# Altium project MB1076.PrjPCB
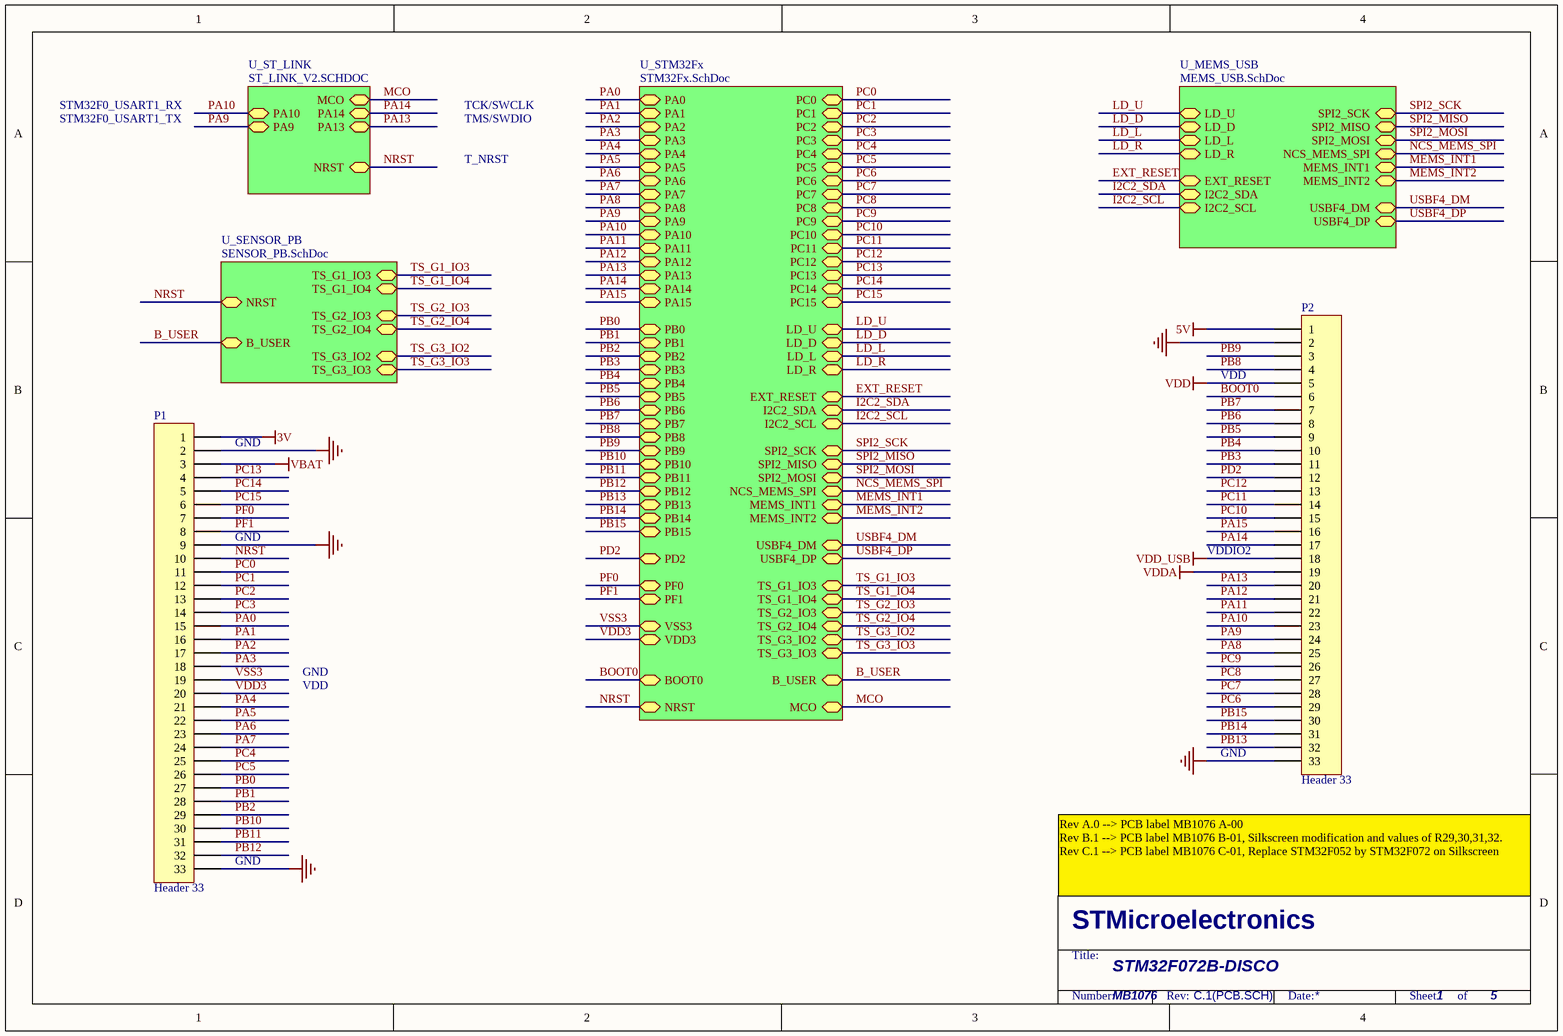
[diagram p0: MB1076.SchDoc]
5 sheets, 142 parts. Net scope: hierarchical (ports join the sheet entries above them; power ports are global).
Sheets:
  MB1076.SchDoc
    U_ST_LINK = ST_LINK_V2.SCHDOC
    U_MEMS_USB = MEMS_USB.SchDoc
    U_STM32Fx = STM32Fx.SchDoc
    U_SENSOR_PB = SENSOR_PB.SchDoc

## Sheet MB1076.SchDoc
size A4; DocumentNumber: 1; Revision: C.1(PCB.SCH); SheetNumber: 1; SheetTotal: 5; PageSetup: Record=PageOptions|CenterHorizontal=True|CenterVertical=True|PrintScale=1.00|XCorrection=1.00|YCorrection=1.00|PrintKind=1|BorderSize=5000000|LeftOffset=0|BottomOffset=0|Orientation=2|PaperLength=1000|PaperWidth=1000|Scale=100|PaperSource=15|PrintQuality=1200|MediaType=1|DitherType=10|PaperKind=A4|PrintScaleMode=1

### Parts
P1  Header 33  [HDR1X33]
P2  Header 33  [HDR1X33]

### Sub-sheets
U_MEMS_USB = MEMS_USB.SchDoc: LD_D, LD_U, LD_L, LD_R, EXT_RESET, MEMS_INT1, NCS_MEMS_SPI, MEMS_INT2, SPI2_SCK, SPI2_MISO, SPI2_MOSI, USBF4_DM, USBF4_DP, I2C2_SCL, I2C2_SDA
U_SENSOR_PB = SENSOR_PB.SchDoc: NRST, TS_G1_IO3, TS_G1_IO4, TS_G2_IO3, TS_G2_IO4, TS_G3_IO2, TS_G3_IO3, B_USER
U_ST_LINK = ST_LINK_V2.SCHDOC: PA13, PA14, NRST, MCO, PA10, PA9
U_STM32Fx = STM32Fx.SchDoc: PB8, PC5, PC4, PD2, BOOT0, NRST, PC15, PC14, PF1, PF0, MCO, VSS3, PC0, PC1, PC2, PC3, PC6, PC7, PC8, PC9, PC10, PC11, PC12, PC13, PA0, PA1, PA2, PA3, PA4, PA5, PA6, PA7, PA8, PA9, PA10, PA11, PA12, PA13, PA14, PA15, PB0, PB1, PB2, PB3, PB4, PB5, PB6, PB7, PB9, PB10, PB11, PB12, PB13, PB14, PB15, EXT_RESET, I2C2_SCL, I2C2_SDA, TS_G1_IO3, TS_G1_IO4, TS_G2_IO3, TS_G2_IO4, TS_G3_IO2, TS_G3_IO3, VDD3, B_USER, USBF4_DM, USBF4_DP, LD_D, LD_U, LD_L, LD_R, SPI2_SCK, SPI2_MISO, SPI2_MOSI, MEMS_INT1, NCS_MEMS_SPI, MEMS_INT2

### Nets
3V: P1.1
5V: P2.1
GND: P1.2 P1.9 P1.33 P2.2 P2.33
VBAT: P1.3
VDD: P2.5
VDD_USB: P2.18
VDDA: P2.19
B_USER: P1.15 ; sheet U_STM32Fx/PA0, sheet U_STM32Fx/B_USER, sheet U_SENSOR_PB/B_USER  [also labelled PA0]
BOOT0: P2.6 ; sheet U_STM32Fx/BOOT0
EXT_RESET: P1.26 ; sheet U_MEMS_USB/EXT_RESET, sheet U_STM32Fx/PC5, sheet U_STM32Fx/EXT_RESET  [also labelled PC5]
I2C2_SCL: P1.30 ; sheet U_MEMS_USB/I2C2_SCL, sheet U_STM32Fx/PB10, sheet U_STM32Fx/I2C2_SCL  [also labelled PB10]
I2C2_SDA: P1.31 ; sheet U_MEMS_USB/I2C2_SDA, sheet U_STM32Fx/PB11, sheet U_STM32Fx/I2C2_SDA  [also labelled PB11]
LD_D: P2.28 ; sheet U_MEMS_USB/LD_D, sheet U_STM32Fx/PC7, sheet U_STM32Fx/LD_D  [also labelled PC7]
LD_L: P2.27 ; sheet U_MEMS_USB/LD_L, sheet U_STM32Fx/PC8, sheet U_STM32Fx/LD_L  [also labelled PC8]
LD_R: P2.26 ; sheet U_MEMS_USB/LD_R, sheet U_STM32Fx/PC9, sheet U_STM32Fx/LD_R  [also labelled PC9]
LD_U: P2.29 ; sheet U_MEMS_USB/LD_U, sheet U_STM32Fx/PC6, sheet U_STM32Fx/LD_U  [also labelled PC6]
MCO: sheet U_ST_LINK/MCO, sheet U_STM32Fx/MCO
MEMS_INT1: P1.12 ; sheet U_MEMS_USB/MEMS_INT1, sheet U_STM32Fx/PC1, sheet U_STM32Fx/MEMS_INT1  [also labelled PC1]
MEMS_INT2: P1.13 ; sheet U_MEMS_USB/MEMS_INT2, sheet U_STM32Fx/PC2, sheet U_STM32Fx/MEMS_INT2  [also labelled PC2]
NCS_MEMS_SPI: P1.11 ; sheet U_MEMS_USB/NCS_MEMS_SPI, sheet U_STM32Fx/PC0, sheet U_STM32Fx/NCS_MEMS_SPI  [also labelled PC0]
NRST: P1.10 ; sheet U_ST_LINK/NRST, sheet U_STM32Fx/NRST, sheet U_SENSOR_PB/NRST
PA1: P1.16 ; sheet U_STM32Fx/PA1
PA2: P1.17 ; sheet U_STM32Fx/PA2
PA3: P1.18 ; sheet U_STM32Fx/PA3
PA4: P1.21 ; sheet U_STM32Fx/PA4
PA5: P1.22 ; sheet U_STM32Fx/PA5
PA6: P1.23 ; sheet U_STM32Fx/PA6
PA7: P1.24 ; sheet U_STM32Fx/PA7
PA8: P2.25 ; sheet U_STM32Fx/PA8
PA9: P2.24 ; sheet U_ST_LINK/PA9, sheet U_STM32Fx/PA9
PA10: P2.23 ; sheet U_ST_LINK/PA10, sheet U_STM32Fx/PA10
PA11: P2.22 ; sheet U_STM32Fx/PA11
PA12: P2.21 ; sheet U_STM32Fx/PA12
PA13: P2.20 ; sheet U_ST_LINK/PA13, sheet U_STM32Fx/PA13
PA14: P2.17 ; sheet U_ST_LINK/PA14, sheet U_STM32Fx/PA14
PA15: P2.16 ; sheet U_STM32Fx/PA15
PB0: P1.27 ; sheet U_STM32Fx/PB0
PB1: P1.28 ; sheet U_STM32Fx/PB1
PB2: P1.29 ; sheet U_STM32Fx/PB2
PB3: P2.11 ; sheet U_STM32Fx/PB3
PB4: P2.10 ; sheet U_STM32Fx/PB4
PB5: P2.9 ; sheet U_STM32Fx/PB5
PB6: P2.8 ; sheet U_STM32Fx/PB6
PB7: P2.7 ; sheet U_STM32Fx/PB7
PB8: P2.4 ; sheet U_STM32Fx/PB8
PB9: P2.3 ; sheet U_STM32Fx/PB9
PB12: P1.32 ; sheet U_STM32Fx/PB12
PB13: P2.32 ; sheet U_MEMS_USB/SPI2_SCK, sheet U_STM32Fx/PB13, sheet U_STM32Fx/SPI2_SCK  [also labelled SPI2_SCK]
PB14: P2.31 ; sheet U_MEMS_USB/SPI2_MISO, sheet U_STM32Fx/PB14, sheet U_STM32Fx/SPI2_MISO  [also labelled SPI2_MISO]
PB15: P2.30 ; sheet U_MEMS_USB/SPI2_MOSI, sheet U_STM32Fx/PB15, sheet U_STM32Fx/SPI2_MOSI  [also labelled SPI2_MOSI]
PC3: P1.14 ; sheet U_STM32Fx/PC3
PC4: P1.25 ; sheet U_STM32Fx/PC4
PC10: P2.15 ; sheet U_STM32Fx/PC10
PC11: P2.14 ; sheet U_STM32Fx/PC11
PC12: P2.13 ; sheet U_STM32Fx/PC12
PC13: P1.4 ; sheet U_STM32Fx/PC13
PC14: P1.5 ; sheet U_STM32Fx/PC14
PC15: P1.6 ; sheet U_STM32Fx/PC15
PD2: P2.12 ; sheet U_STM32Fx/PD2
PF0: P1.7 ; sheet U_STM32Fx/PF0
PF1: P1.8 ; sheet U_STM32Fx/PF1
TS_G1_IO3: sheet U_STM32Fx/TS_G1_IO3, sheet U_SENSOR_PB/TS_G1_IO3
TS_G1_IO4: sheet U_STM32Fx/TS_G1_IO4, sheet U_SENSOR_PB/TS_G1_IO4
TS_G2_IO3: sheet U_STM32Fx/TS_G2_IO3, sheet U_SENSOR_PB/TS_G2_IO3
TS_G2_IO4: sheet U_STM32Fx/TS_G2_IO4, sheet U_SENSOR_PB/TS_G2_IO4
TS_G3_IO2: sheet U_STM32Fx/TS_G3_IO2, sheet U_SENSOR_PB/TS_G3_IO2
TS_G3_IO3: sheet U_STM32Fx/TS_G3_IO3, sheet U_SENSOR_PB/TS_G3_IO3
USBF4_DM: sheet U_MEMS_USB/USBF4_DM, sheet U_STM32Fx/USBF4_DM
USBF4_DP: sheet U_MEMS_USB/USBF4_DP, sheet U_STM32Fx/USBF4_DP
VDD3: P1.20 ; sheet U_STM32Fx/VDD3
VSS3: P1.19 ; sheet U_STM32Fx/VSS3

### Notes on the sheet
- STM32F0_USART1_RX
- TCK/SWCLK
- STM32F0_USART1_TX
- TMS/SWDIO
- T_NRST
- VDD
- (near P1) GND
- VDDIO2
- GND
- Rev A.0 --> PCB label MB1076 A-00
  Rev B.1 --> PCB label MB1076 B-01, Silkscreen modification and values of R29,30,31,32.
  Rev C.1 --> PCB label MB1076 C-01, Replace STM32F052 by STM32F072 on Silkscreen
- STM32F072B-DISCO
- MB1076
- 1

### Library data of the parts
P1 P2 = Header 33: Header, 33-Pin

## Sheet ST_LINK_V2.SCHDOC
size A4; DocumentNumber: 2; Revision: C.1(PCB.SCH); SheetNumber: 2; SheetTotal: 5
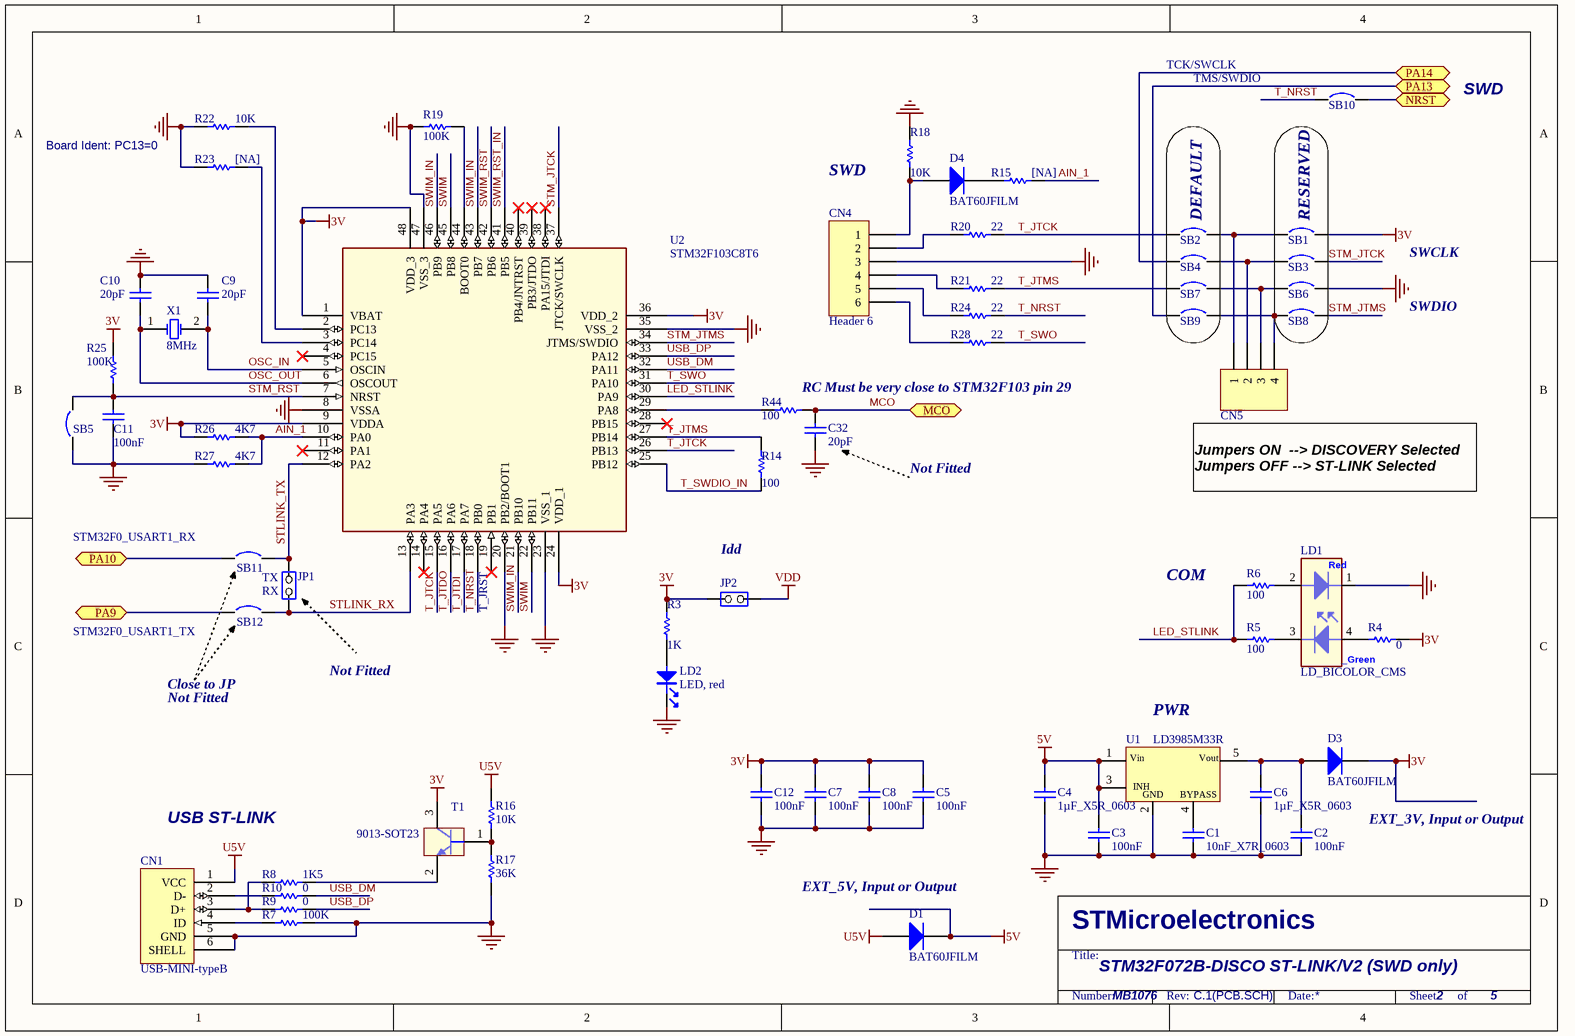
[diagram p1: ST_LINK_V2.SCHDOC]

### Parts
C1  10nF_X7R_0603  [0603C]
C2  100nF  [0402C]
C3  100nF  [0402C]
C4  1µF_X5R_0603  [0603C]
C5  100nF  [0402C]
C6  1µF_X5R_0603  [0603C]
C7  100nF  [0402C]
C8  100nF  [0402C]
C9  20pF  [0402C]
C10  20pF  [0402C]
C11  100nF  [0402C]
C12  100nF  [0402C]
C32  20pF  [0402C]
CN1  USB-MINI-typeB  [USB-MINI-B-SMD]
CN4  Header 6  [HDR1X6]
CN5  Header 4  [Header 4]  (value not drawn)
D1  BAT60JFILM  [SOD323/A]
D3  BAT60JFILM  [SOD323/A]
D4  BAT60JFILM  [SOD323/A]
JP1  JP2  [SIP2/2.54]  (value not drawn)
JP2  (no value)  [SIP2/2.54]
LD1  LD_BICOLOR_CMS  [HSMF-A201]
LD2  LED, red  [0603D]
R3  1K  [0402R]
R4  0  [0402R]
R5  100  [0402R]
R6  100  [0402R]
R7  100K  [0402R]
R8  1K5  [0402R]
R9  0  [0402R]
R10  0  [0402R]
R14  100  [0402R]
R15  [NA]  [0402R]
R16  10K  [0402R]
R17  36K  [0402R]
R18  10K  [0402R]
R19  100K  [0402R]
R20  22  [0402R]
R21  22  [0402R]
R22  10K  [0402R]
R23  [NA]  [0402R]
R24  22  [0402R]
R25  100K  [0402R]
R26  4K7  [0402R]
R27  4K7  [0402R]
R28  22  [0402R]
R44  100  [0402R]
SB1  Circuit Breaker  [JP2_SMD]  (value not drawn)
SB2  Circuit Breaker  [JP2_SMD]  (value not drawn)
SB3  Circuit Breaker  [JP2_SMD]  (value not drawn)
SB4  Circuit Breaker  [JP2_SMD]  (value not drawn)
SB5  Circuit Breaker  [JP2_SMD]  (value not drawn)
SB6  Circuit Breaker  [JP2_SMD]  (value not drawn)
SB7  Circuit Breaker  [JP2_SMD]  (value not drawn)
SB8  Circuit Breaker  [JP2_SMD]  (value not drawn)
SB9  Circuit Breaker  [JP2_SMD]  (value not drawn)
SB10  Circuit Breaker  [JP2_SMD]  (value not drawn)
SB11  Circuit Breaker  [JP2_SMD]  (value not drawn)
SB12  Circuit Breaker  [JP2_SMD]  (value not drawn)
T1  9013-SOT23  [SOT-23]
U1  LD3985M33R  [SOT-23-5L]
U2  STM32F103C8T6  [QFP48 7X7]
X1  8MHz  [XTAL1]

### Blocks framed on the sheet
DEFAULT: SB2 SB4 SB7 SB9
RESERVED: SB1 SB3 SB6 SB8

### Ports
MCO, NRST, PA9, PA10, PA13, PA14

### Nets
3V: C5.2 C7.2 C8.2 C12.2 D3.2(K) JP2.1(COMMON) R3.2 R4.2 R25.2 R26.1 SB1.2 T1.3(C) U2.1(VBAT) U2.9(VDDA) U2.24(VDD_1) U2.36(VDD_2) U2.48(VDD_3)
5V: C3.2 C4.2 D1.2(K) U1.1(Vin) U1.3(CE)
GND: C1.1 C2.1 C3.1 C4.1 C5.1 C6.2 C7.1 C8.1 C9.2 C10.2 C11.1 C12.1 C32.1 CN1.5(GND) CN1.6(SHELL) CN4.3 LD1.1 LD2.2 R7.2 R17.1 R18.2 R19.1 R22.1 R23.1 R27.1 SB5.1 SB6.2 U1.2(GND) U2.8(VSSA) U2.20(PB2/BOOT1) U2.23(VSS_1) U2.35(VSS_2) U2.47(VSS_3)
U5V: CN1.1(VCC) D1.1(A) R16.2
VDD: JP2.2(NO)
AIN_1: R15.2 R26.2 R27.2 U2.10(PA0)
LED_STLINK: R5.1 R6.1 U2.30(PA9)
MCO: C32.2 R44.2 ; port MCO
NRST: SB10.2 ; port NRST
OSC_IN: C9.1 U2.5(OSCIN) X1.2(OSC2)
OSC_OUT: C10.1 U2.6(OSCOUT) X1.1(OSC1)
PA9: SB12.1 ; port PA9
PA10: SB11.1 ; port PA10
PA13: SB9.1 ; port PA13
PA14: SB4.1 ; port PA14
STLINK_RX: JP1.1(COMMON) SB12.2 U2.13(PA3)
STLINK_TX: JP1.2(NO) SB11.2 U2.12(PA2)
STM_JTCK: SB3.2 U2.37(JTCK/SWCLK)
STM_JTMS: SB8.2 U2.34(JTMS/SWDIO)
STM_RST: C11.2 R25.1 SB5.2 U2.7(NRST)
SWIM: U2.22(PB11) U2.45(PB8)
SWIM_IN: U2.21(PB10) U2.43(PB7) U2.46(PB9)
SWIM_RST: U2.42(PB6)
SWIM_RST_IN: U2.41(PB5)
T_JTCK: R20.2 SB2.1 U2.15(PA5) U2.26(PB13)
T_JTDI: U2.17(PA7)
T_JTDO: U2.16(PA6)
T_JTMS: R14.2 R21.2 SB7.1 U2.27(PB14)
T_NRST: R24.2 SB10.1 U2.18(PB0)
T_SWDIO_IN: R14.1 U2.25(PB12)
T_SWO: R28.2 U2.31(PA10)
USB_DM: R10.2 U2.32(PA11)
USB_DP: R9.2 U2.33(PA12)
NetC1_2: C1.2 U1.4(BYPASS)
NetC2_2: C2.2 C6.1 D3.1(A) U1.5(Vout)
NetCN1_2: CN1.2(D-) R10.1
NetCN1_3: CN1.3(D+) R8.1 R9.1
NetCN1_4: CN1.4(ID) R7.1
NetCN4_1: CN4.1 D4.1(A) R18.1
NetCN4_2: CN4.2 R20.1
NetCN4_4: CN4.4 R21.1
NetCN4_5: CN4.5 R24.1
NetCN4_6: CN4.6 R28.1
NetCN5_1: CN5.1 SB1.1 SB2.2
NetCN5_2: CN5.2 SB3.1 SB4.2
NetCN5_3: CN5.3 SB6.1 SB7.2
NetCN5_4: CN5.4 SB8.1 SB9.2
NetD4_2: D4.2(K) R15.1
NetLD1_2: LD1.2 R6.2
NetLD1_3: LD1.3 R5.2
NetLD1_4: LD1.4 R4.1
NetLD2_1: LD2.1 R3.1
NetR8_2: R8.2 T1.2(E)
NetR16_1: R16.1 R17.2 T1.1(B)
NetR19_2: R19.2 U2.44(BOOT0)
NetR22_2: R22.2 U2.2(PC13)
NetR23_2: R23.2 U2.3(PC14)
NetR44_1: R44.1 U2.29(PA8)

Not connected (* = marked no-connect by the designer): U2 4(PC15)* 11(PA1)* 14(PA4)* 19(PB1)* 28(PB15)* 38(PA15/JTDI)* 39(PB3/JTDO)* 40(PB4/JNTRST)*

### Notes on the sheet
- TCK/SWCLK
- TMS/SWDIO
- SWD
- Board Ident: PC13=0
- SWCLK
- SWDIO
- (near R44) RC Must be very close to STM32F103 pin 29
- Not Fitted
- Jumpers ON  --> DISCOVERY Selected
  Jumpers OFF --> ST-LINK Selected
- STM32F0_USART1_RX
- TX
- (near JP2) Idd
- COM
- STM32F0_USART1_TX
- RX
- (near U2) T_JRST
- Close to JP
- (near U1) PWR
- USB ST-LINK
- EXT_3V, Input or Output
- (near D1) EXT_5V, Input or Output
- STM32F072B-DISCO ST-LINK/V2 (SWD only)
- MB1076

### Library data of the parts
C1 = CAP SMD 0603  X7R 10000PF 50V 10%: 0603  X7R 10NF; Order code RS: 2040779; Rated voltage: 50V; Tolerance: 10%
C2 C3 C5 C7 C8 C11 C12 = Capacitor_ST: Capacitor 0402 / 0603 / 0805
C4 C6 = CAP SMD 0603  X5R 1µF 25V 10%: 0603  X5R 1µF; Rated voltage: 25V; Tolerance: 10%
C9 C10 C32 = Capacitor_ST: Capacitor 0402 / 0603 / 0805; Value: 100nF
CN1 = USB-MINI-typeB connector: Manuf_Part_1: 5075BMR-05-SM; Manuf_Part_2: 218205M1110T; Manuf_2: lyconn; Description: USB,MINI-USB-5P/F, 5075BMR-05-M
CN4 = Header 6: Header, 6-Pin
CN5 = Header 4: Header, 4-Pin
D1 D3 D4 = BAT60JFILM: Manuf_1: STM; Provided: ST; ECCN_US/EU: EAR99/NEC
JP1 = JP2: Fitted: NO
JP2 = JP2
LD1 = LD_BICOLOR_CMS: Bicolor Led; Manuf_Part_1: HSMF-A201-A00J1; Manuf_1: Avago Technologies; Manuf_2: everluck; Manuf_Part_2: LE-RGW35280; Ref St: xxxxxx
LD2 = LED_red: LED, red, 0603; Manuf_1: everlight; Manuf_Part_1: 19-213-R6C-AP1Q2B/3T; Description: LED,red,0603,19-213-R6C-AP1Q2B/3T,everlight
R3-R10 R14 R17 R19-R21 R24-R28 R44 = Resistor_ST: Resistor 0402 / 0603 / 0805; Description: Resistor 0402 or 0603 or 0805; Value: 10K
R15 R23 = Resistor_ST: Resistor 0402 / 0603 / 0805; Description: Resistor 0402 or 0603 or 0805; Value: 10K; Fitted: NO
R16 R18 R22 = Resistor_ST: Resistor 0402 / 0603 / 0805; Description: Resistor 0402 or 0603 or 0805
SB1 SB3 SB6 SB8 SB10 = Circuit Breaker: Solder: YES
SB2 SB4 SB5 SB7 SB9 SB11 SB12 = Circuit Breaker: Solder: NO
T1 = 9013-SOT23: NPN Bipolar Transistor; Description: NPN Bipolar Transistor, SOT-23 Footprint
U1 = LD3985M33R: Ultra low drop-low noise BiCMOS voltage, regulators low ESR capacitors compatible; Manuf_1: STM; Provided: ST; Ref St: 9176161; ECCN_US/EU: EAR99/NEC
U2 = STM32F103C8T6: Medium-density performance line ARM-based 32-bit MCU with 64KB Flash; Manuf_1: STM; Ref St: 9175981; Provided: ST; ECCN_US/EU: 3A991A2/NEC
X1 = XTAL: Crystal Oscillator,8Mhz,20PF,20PPM,-10-70 degree,DIP,HC-49S; Manuf_Part_1: 9SL8000020AFXHF0

## Sheet MEMS_USB.SchDoc
size A4; DocumentNumber: 6; Revision: C.1(PCB.SCH); SheetNumber: 4; SheetTotal: 5
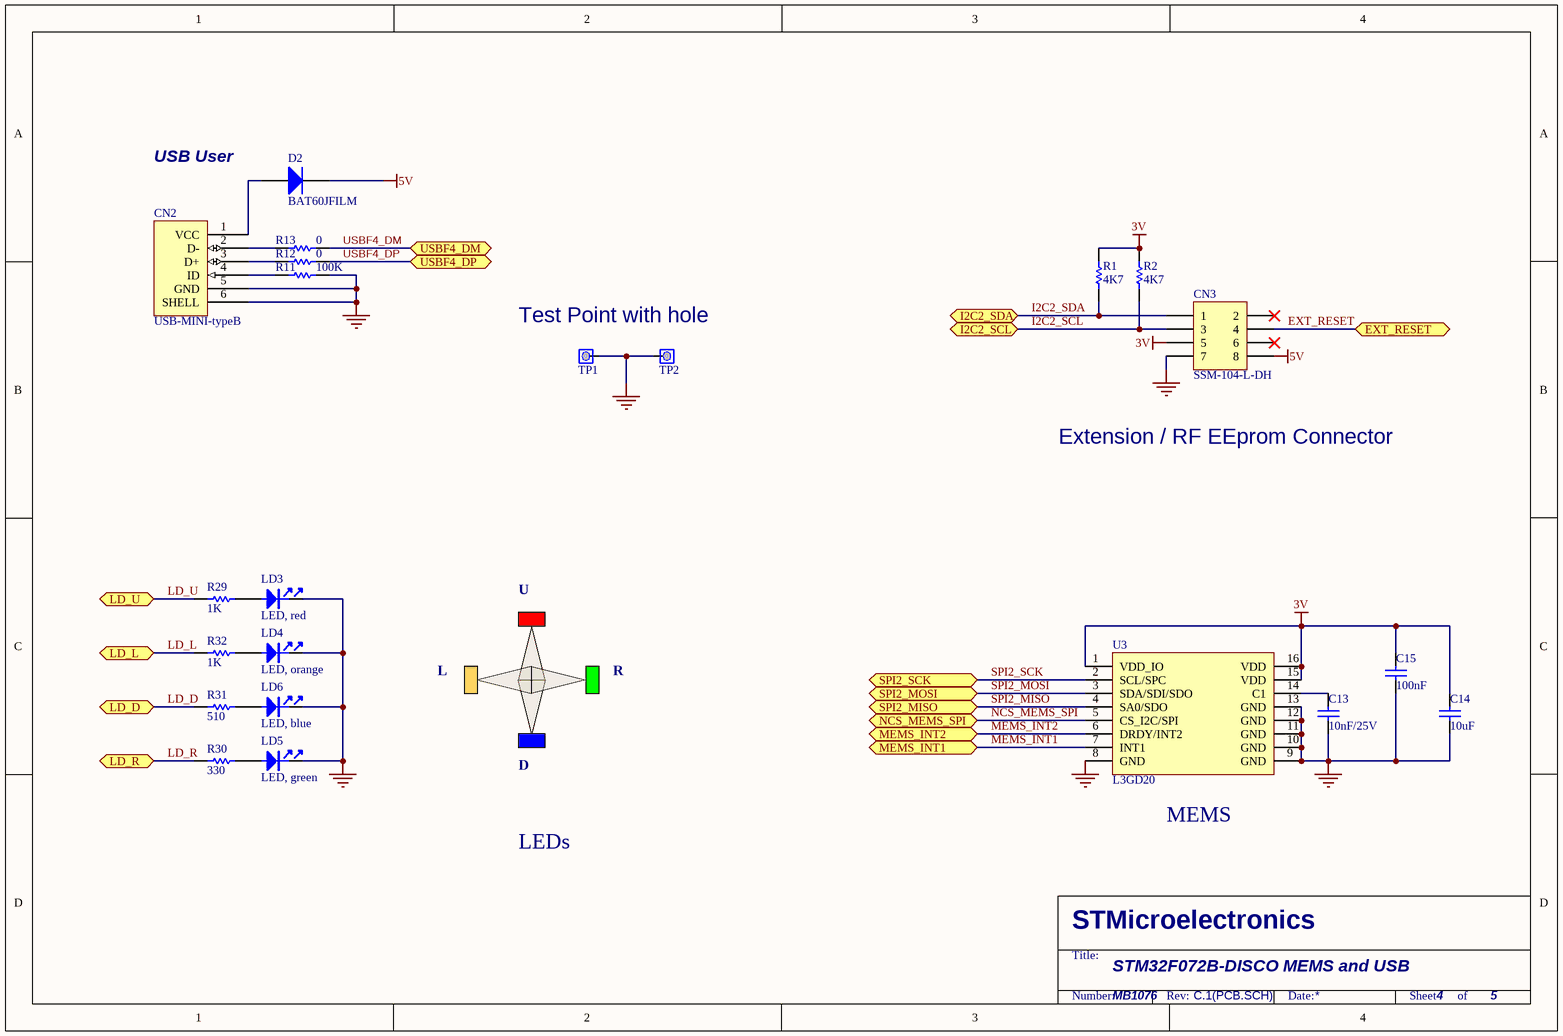
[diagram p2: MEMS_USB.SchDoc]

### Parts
C13  10nF/25V  [0603C]
C14  10uF  [0603C]
C15  100nF  [0402C]
CN2  USB-MINI-typeB  [USB-MINI-B-SMD]
CN3  SSM-104-L-DH  [SSM-104-L-DH]
D2  BAT60JFILM  [SOD323/A]
LD3  LED, red  [0603D]
LD4  LED, orange  [0603D]
LD5  LED, green  [0603D]
LD6  LED, blue  [0603D]
R1  4K7  [0402R]
R2  4K7  [0402R]
R11  100K  [0402R]
R12  0  [0402R]
R13  0  [0402R]
R29  1K  [0603R]
R30  330  [0603R]
R31  510  [0603R]
R32  1K  [0603R]
TP1  Test point 1 pin with hole  [SIP1/2.54]  (value not drawn)
TP2  Test point 1 pin with hole  [SIP1/2.54]  (value not drawn)
U3  L3GD20  [LGA16-4x4]

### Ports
EXT_RESET, I2C2_SCL, I2C2_SDA, LD_D, LD_L, LD_R, LD_U, MEMS_INT1, MEMS_INT2, NCS_MEMS_SPI, SPI2_MISO, SPI2_MOSI, SPI2_SCK, USBF4_DM, USBF4_DP

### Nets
3V: C14.2 C15.2 CN3.5 R1.2 R2.2 U3.1(VDD_IO) U3.15(VDD) U3.16(VDD)
5V: CN3.8 D2.2(K)
GND: C13.1 C14.1 C15.1 CN2.5(GND) CN2.6(SHELL) CN3.7 LD3.2 LD4.2 LD5.2 LD6.2 R11.2 TP1.1(COMMON) TP2.1(COMMON) U3.8(GND) U3.9(GND) U3.10(GND) U3.11(GND) U3.12(GND) U3.13(GND)
EXT_RESET: CN3.4 ; port EXT_RESET
I2C2_SCL: CN3.3 R2.1 ; port I2C2_SCL
I2C2_SDA: CN3.1 R1.1 ; port I2C2_SDA
LD_D: R31.1 ; port LD_D
LD_L: R32.1 ; port LD_L
LD_R: R30.1 ; port LD_R
LD_U: R29.1 ; port LD_U
MEMS_INT1: U3.7(INT1) ; port MEMS_INT1
MEMS_INT2: U3.6(DRDY/INT2) ; port MEMS_INT2
NCS_MEMS_SPI: U3.5(CS_I2C/SPI) ; port NCS_MEMS_SPI
SPI2_MISO: U3.4(SA0/SDO) ; port SPI2_MISO  [project net PB14]
SPI2_MOSI: U3.3(SDA/SDI/SDO) ; port SPI2_MOSI  [project net PB15]
SPI2_SCK: U3.2(SCL/SPC) ; port SPI2_SCK  [project net PB13]
USBF4_DM: R13.2 ; port USBF4_DM
USBF4_DP: R12.2 ; port USBF4_DP
NetC13_2: C13.2 U3.14(C1)
NetCN2_1: CN2.1(VCC) D2.1(A)
NetCN2_2: CN2.2(D-) R13.1
NetCN2_3: CN2.3(D+) R12.1
NetCN2_4: CN2.4(ID) R11.1
NetLD3_1: LD3.1 R29.2
NetLD4_1: LD4.1 R32.2
NetLD5_1: LD5.1 R30.2
NetLD6_1: LD6.1 R31.2

Not connected (* = marked no-connect by the designer): CN3 2* 6*

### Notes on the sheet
- USB User
- Test Point with hole
- Extension / RF EEprom Connector
- U
- L
- R
- D
- LEDs
- (near U3) MEMS
- STM32F072B-DISCO MEMS and USB
- MB1076

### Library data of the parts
C13 C14 = CAP: Capacitor; Value: 100nF
C15 = Capacitor_ST: Capacitor 0402 / 0603 / 0805
CN2 = USB-MINI-typeB connector: Manuf_Part_1: 5075BMR-05-SM
CN3 = SSM-104-L-DH: Header, 5-Pin, Dual row
D2 = BAT60JFILM: as D1 on sheet ST_LINK_V2
LD3 = LED_red: as LD2 on sheet ST_LINK_V2
LD4 = LED_orange: LED, orange, 0603; Manuf_1: everlight; Manuf_Part_1: 19-217/S2C-AM2N2VY/3T; Description: LED,orange,0603,19-217/S2C-AM2N2VY/3T,everlight
LD5 = LED_green: LED, green, 0603; Manuf_1: everlight; Manuf_Part_1: 19-213SYGC/S530-E2/TR8; Description: LED,green,0603,19-213SYGC/S530-E2/TR8,everlight
LD6 = LED_blue: LED, blue, 0603; Manuf_1: everlight; Manuf_Part_1: 19-217/BHC-ZL1M2RY/3T; Description: LED,Blue,0603,19-217/BHC-ZL1M2RY/3T,everlight
R1 R2 R11-R13 R29-R32 = Resistor_ST: as R3 on sheet ST_LINK_V2
TP1 TP2 = TP1: Test Point; Fitted: NO
U3 = L3GD20: MEMS motion sensor three-axis digital output gyroscopeelerometer; Manuf_1: STM; Manuf_Part_1: L3GD20TR; Provided: ST; Ref St: 9177042; ECCN_US/EU: EAR99/NEC

## Sheet STM32Fx.SchDoc
size A4; DocumentNumber: 3; Revision: C.1(PCB.SCH); SheetNumber: 3; SheetTotal: 5
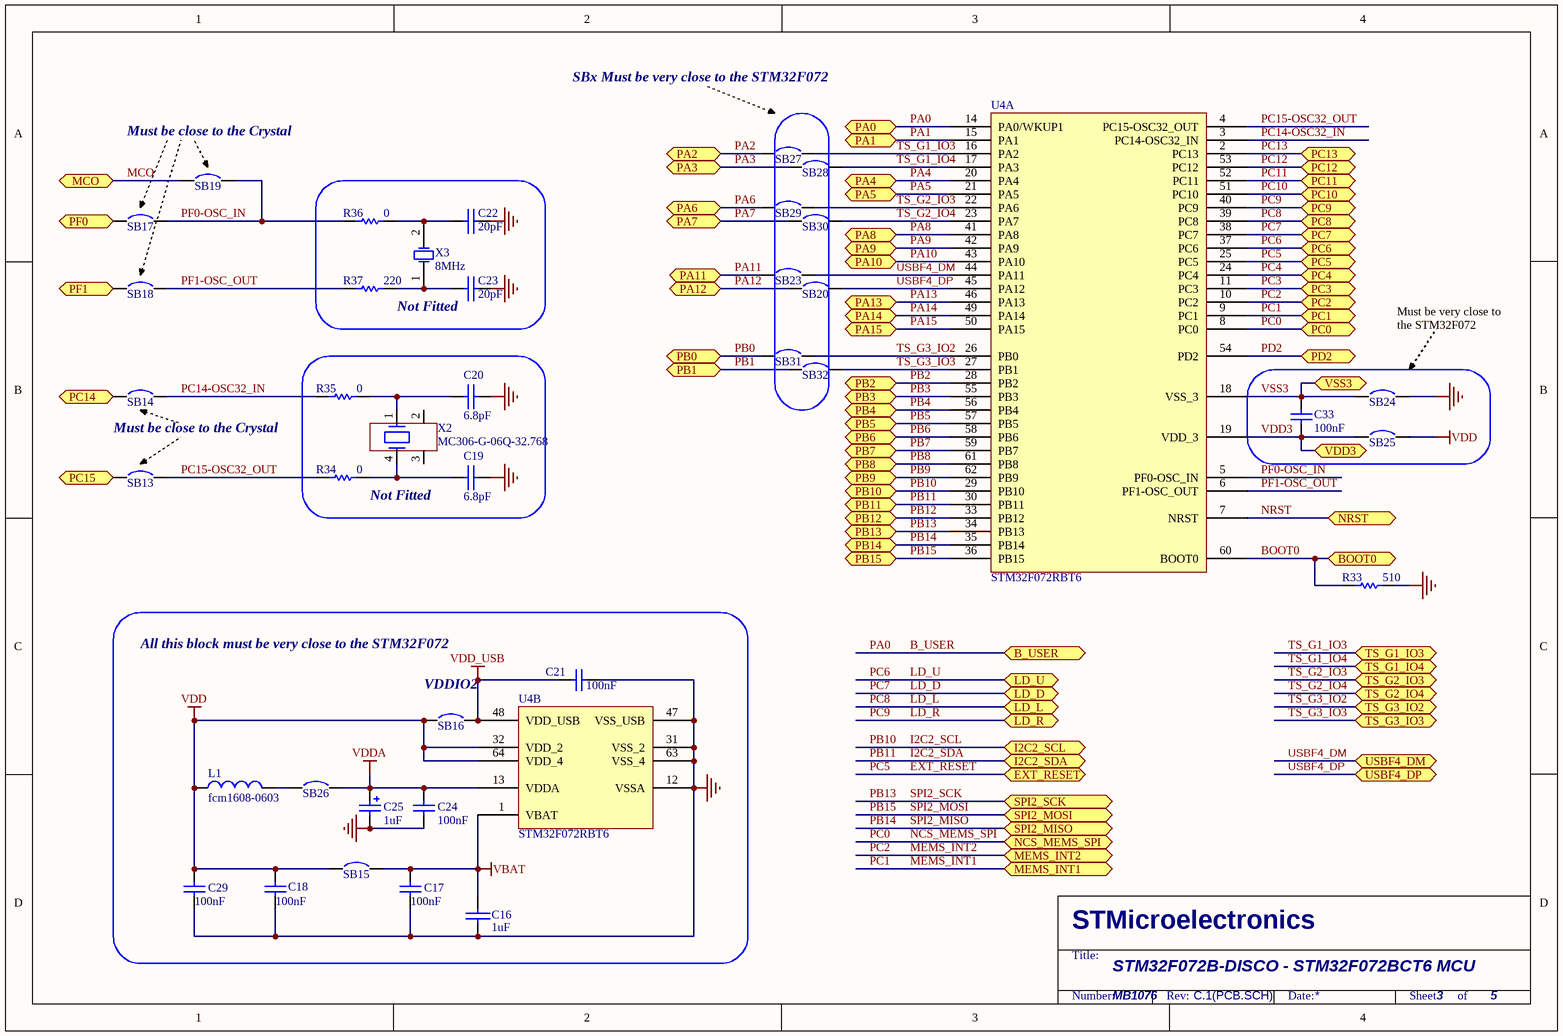
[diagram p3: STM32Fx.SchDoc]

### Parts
C16  1uF  [0603C]
C17  100nF  [0603C]
C18  100nF  [0603C]
C19  6.8pF  [0603C]
C20  6.8pF  [0603C]
C21  100nF  [0603C]
C22  20pF  [0603C]
C23  20pF  [0603C]
C24  100nF  [0603C]
C25  1uF  [CASE-AA]
C29  100nF  [0603C]
C33  100nF  [0402C]
L1  fcm1608-0603  [0603L]
R33  510  [0402R]
R34  0  [0402R]
R35  0  [0402R]
R36  0  [0402R]
R37  220  [0402R]
SB13  Circuit Breaker  [JP2_SMD]  (value not drawn)
SB14  Circuit Breaker  [JP2_SMD]  (value not drawn)
SB15  Circuit Breaker  [JP2_SMD]  (value not drawn)
SB16  Circuit Breaker  [JP2_SMD]  (value not drawn)
SB17  Circuit Breaker  [JP2_SMD]  (value not drawn)
SB18  Circuit Breaker  [JP2_SMD]  (value not drawn)
SB19  Circuit Breaker  [JP2_SMD]  (value not drawn)
SB20  Circuit Breaker  [JP2_SMD]  (value not drawn)
SB23  Circuit Breaker  [JP2_SMD]  (value not drawn)
SB24  Circuit Breaker  [JP2_SMD]  (value not drawn)
SB25  Circuit Breaker  [JP2_SMD]  (value not drawn)
SB26  Circuit Breaker  [JP2_SMD]  (value not drawn)
SB27  Circuit Breaker  [JP2_SMD]  (value not drawn)
SB28  Circuit Breaker  [JP2_SMD]  (value not drawn)
SB29  Circuit Breaker  [JP2_SMD]  (value not drawn)
SB30  Circuit Breaker  [JP2_SMD]  (value not drawn)
SB31  Circuit Breaker  [JP2_SMD]  (value not drawn)
SB32  Circuit Breaker  [JP2_SMD]  (value not drawn)
U4  STM32F072RBT6  [QFP64]  (parts A,B of 2)
X2  MC306-G-06Q-32.768  [MC306-CRYSTAL]
X3  8MHz  [XTAL1]

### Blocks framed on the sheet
Not Fitted: C22 C23 R36 R37 X3
Not Fitted: C19 C20 R34 R35 X2

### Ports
B_USER, BOOT0, EXT_RESET, I2C2_SCL, I2C2_SDA, LD_D, LD_L, LD_R, LD_U, MCO, MEMS_INT1, MEMS_INT2, NCS_MEMS_SPI, NRST, PA0, PA1, PA2, PA3, PA4, PA5, PA6, PA7, PA8, PA9, PA10, PA11, PA12, PA13, PA14, PA15, PB0, PB1, PB2, PB3, PB4, PB5, PB6, PB7, PB8, PB9, PB10, PB11, PB12, PB13, PB14, PB15, PC0, PC1, PC2, PC3, PC4, PC5, PC6, PC7, PC8, PC9, PC10, PC11, PC12, PC13, PC14, PC15, PD2, PF0, PF1, SPI2_MISO, SPI2_MOSI, SPI2_SCK, TS_G1_IO3, TS_G1_IO4, TS_G2_IO3, TS_G2_IO4, TS_G3_IO2, TS_G3_IO3, USBF4_DM, USBF4_DP, VDD3, VSS3

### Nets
GND: C16.2 C17.1 C18.2 C19.2 C20.2 C21.1 C22.1 C23.1 C24.1 C25.2 C29.1 R33.2 SB24.2 U4.12(VSSA) U4.31(VSS_2) U4.47(VSS_USB) U4.63(VSS_4)
VBAT: C16.1 C17.2 SB15.2 U4.1(VBAT)
VDD: C18.1 C29.2 L1.1 SB15.1 SB16.1 SB25.2 U4.32(VDD_2) U4.64(VDD_4)
VDD_USB: C21.2 SB16.2 U4.48(VDD_USB)
VDDA: C24.2 C25.1 SB26.2 U4.13(VDDA)
B_USER: U4.14(PA0/WKUP1) ; port PA0, port B_USER  [also labelled PA0]
BOOT0: R33.1 U4.60(BOOT0) ; port BOOT0
EXT_RESET: U4.25(PC5) ; port PC5, port EXT_RESET  [also labelled PC5]
I2C2_SCL: U4.29(PB10) ; port PB10, port I2C2_SCL  [also labelled PB10]
I2C2_SDA: U4.30(PB11) ; port PB11, port I2C2_SDA  [also labelled PB11]
LD_D: U4.38(PC7) ; port PC7, port LD_D  [also labelled PC7]
LD_L: U4.39(PC8) ; port PC8, port LD_L  [also labelled PC8]
LD_R: U4.40(PC9) ; port PC9, port LD_R  [also labelled PC9]
LD_U: U4.37(PC6) ; port PC6, port LD_U  [also labelled PC6]
MCO: SB19.1 ; port MCO
MEMS_INT1: U4.9(PC1) ; port PC1, port MEMS_INT1  [also labelled PC1]
MEMS_INT2: U4.10(PC2) ; port PC2, port MEMS_INT2  [also labelled PC2]
NCS_MEMS_SPI: U4.8(PC0) ; port PC0, port NCS_MEMS_SPI  [also labelled PC0]
NRST: U4.7(NRST) ; port NRST
PA1: U4.15(PA1) ; port PA1
PA2: SB27.1 ; port PA2
PA3: SB28.1 ; port PA3
PA4: U4.20(PA4) ; port PA4
PA5: U4.21(PA5) ; port PA5
PA6: SB29.1 ; port PA6
PA7: SB30.1 ; port PA7
PA8: U4.41(PA8) ; port PA8
PA9: U4.42(PA9) ; port PA9
PA10: U4.43(PA10) ; port PA10
PA11: SB23.1 ; port PA11
PA12: SB20.1 ; port PA12
PA13: U4.46(PA13) ; port PA13
PA14: U4.49(PA14) ; port PA14
PA15: U4.50(PA15) ; port PA15
PB0: SB31.1 ; port PB0
PB1: SB32.1 ; port PB1
PB2: U4.28(PB2) ; port PB2
PB3: U4.55(PB3) ; port PB3
PB4: U4.56(PB4) ; port PB4
PB5: U4.57(PB5) ; port PB5
PB6: U4.58(PB6) ; port PB6
PB7: U4.59(PB7) ; port PB7
PB8: U4.61(PB8) ; port PB8
PB9: U4.62(PB9) ; port PB9
PB12: U4.33(PB12) ; port PB12
PB13: U4.34(PB13) ; port PB13, port SPI2_SCK  [also labelled SPI2_SCK]
PB14: U4.35(PB14) ; port PB14, port SPI2_MISO  [also labelled SPI2_MISO]
PB15: U4.36(PB15) ; port PB15, port SPI2_MOSI  [also labelled SPI2_MOSI]
PC3: U4.11(PC3) ; port PC3
PC4: U4.24(PC4) ; port PC4
PC10: U4.51(PC10) ; port PC10
PC11: U4.52(PC11) ; port PC11
PC12: U4.53(PC12) ; port PC12
PC13: U4.2(PC13) ; port PC13
PC14: SB14.1 ; port PC14
PC14-OSC32_IN: R35.1 SB14.2 U4.3(PC14-OSC32_IN)
PC15: SB13.1 ; port PC15
PC15-OSC32_OUT: R34.1 SB13.2 U4.4(PC15-OSC32_OUT)
PD2: U4.54(PD2) ; port PD2
PF0: SB17.1 ; port PF0
PF0-OSC_IN: R36.1 SB17.2 SB19.2 U4.5(PF0-OSC_IN)
PF1: SB18.1 ; port PF1
PF1-OSC_OUT: R37.1 SB18.2 U4.6(PF1-OSC_OUT)
TS_G1_IO3: SB27.2 U4.16(PA2) ; port TS_G1_IO3
TS_G1_IO4: SB28.2 U4.17(PA3) ; port TS_G1_IO4
TS_G2_IO3: SB29.2 U4.22(PA6) ; port TS_G2_IO3
TS_G2_IO4: SB30.2 U4.23(PA7) ; port TS_G2_IO4
TS_G3_IO2: SB31.2 U4.26(PB0) ; port TS_G3_IO2
TS_G3_IO3: SB32.2 U4.27(PB1) ; port TS_G3_IO3
USBF4_DM: SB23.2 U4.44(PA11) ; port USBF4_DM
USBF4_DP: SB20.2 U4.45(PA12) ; port USBF4_DP
VDD3: C33.1 SB25.1 U4.19(VDD_3) ; port VDD3
VSS3: C33.2 SB24.1 U4.18(VSS_3) ; port VSS3
NetC19_1: C19.1 R34.2 X2.4
NetC20_1: C20.1 R35.2 X2.1
NetC22_2: C22.2 R36.2 X3.2(OSC2)
NetC23_2: C23.2 R37.2 X3.1(OSC1)
NetL1_2: L1.2 SB26.1

Not connected (* = marked no-connect by the designer): X2 2 3

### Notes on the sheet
- SBx Must be very close to the STM32F072
- (near SB19) Must be close to the Crystal
- Must be very close to the STM32F072
- Must be close to the Crystal
- All this block must be very close to the STM32F072
- (near SB16) VDDIO2
- STM32F072B-DISCO - STM32F072BCT6 MCU
- MB1076

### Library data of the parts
C16 = CAP: Capacitor
C17 C18 C21 C24 C29 = Cap: Capacitor
C19 C20 C22 C23 = CAP: Capacitor; Fitted: NO
C25 = Cap Pol1: Polarized Capacitor (Radial); Value: 10uF
C33 = Capacitor_ST: Capacitor 0402 / 0603 / 0805
L1 = Inductor: Value: 100uH
R33 = Resistor_ST: as R3 on sheet ST_LINK_V2
R34-R37 = res1: Resistor; Value: 1K5; Fitted: NO
SB13-SB18 SB24-SB26 = Circuit Breaker: Solder: YES
SB19 SB20 SB23 SB27-SB32 = Circuit Breaker: Solder: NO
U4 = STM32F072RBT6: ARM-based 32-bit MCU (STM32-STINGRAY-128K-USB); Manuf_1: STM; Provided: ST; Ref St: ref to the Cut; ECCN_US/EU: 3A991A2/NEC
X2 = XTAL_32K: Crystal oscillator for clock,32.768K,6PF,20PPM,-40~85 degree,SMT; Manuf_Part_1: ETMB32.768W060BMPF; Manuf_1: JFVNY; Description: crystal oscillator for clock,32.768K,6PF,20PPM,-40~85 degree,SMT,ETMB32.768W060BMPF; Fitted: NO
X3 = XTAL: Crystal Oscillator,8Mhz,20PF,20PPM,-10-70 degree,DIP,HC-49S; Manuf_Part_1: 9SL8000020AFXHF0; Fitted: NO

## Sheet SENSOR_PB.SchDoc
size A4; DocumentNumber: 6; Revision: C.1(PCB.SCH); SheetNumber: 5; SheetTotal: 5
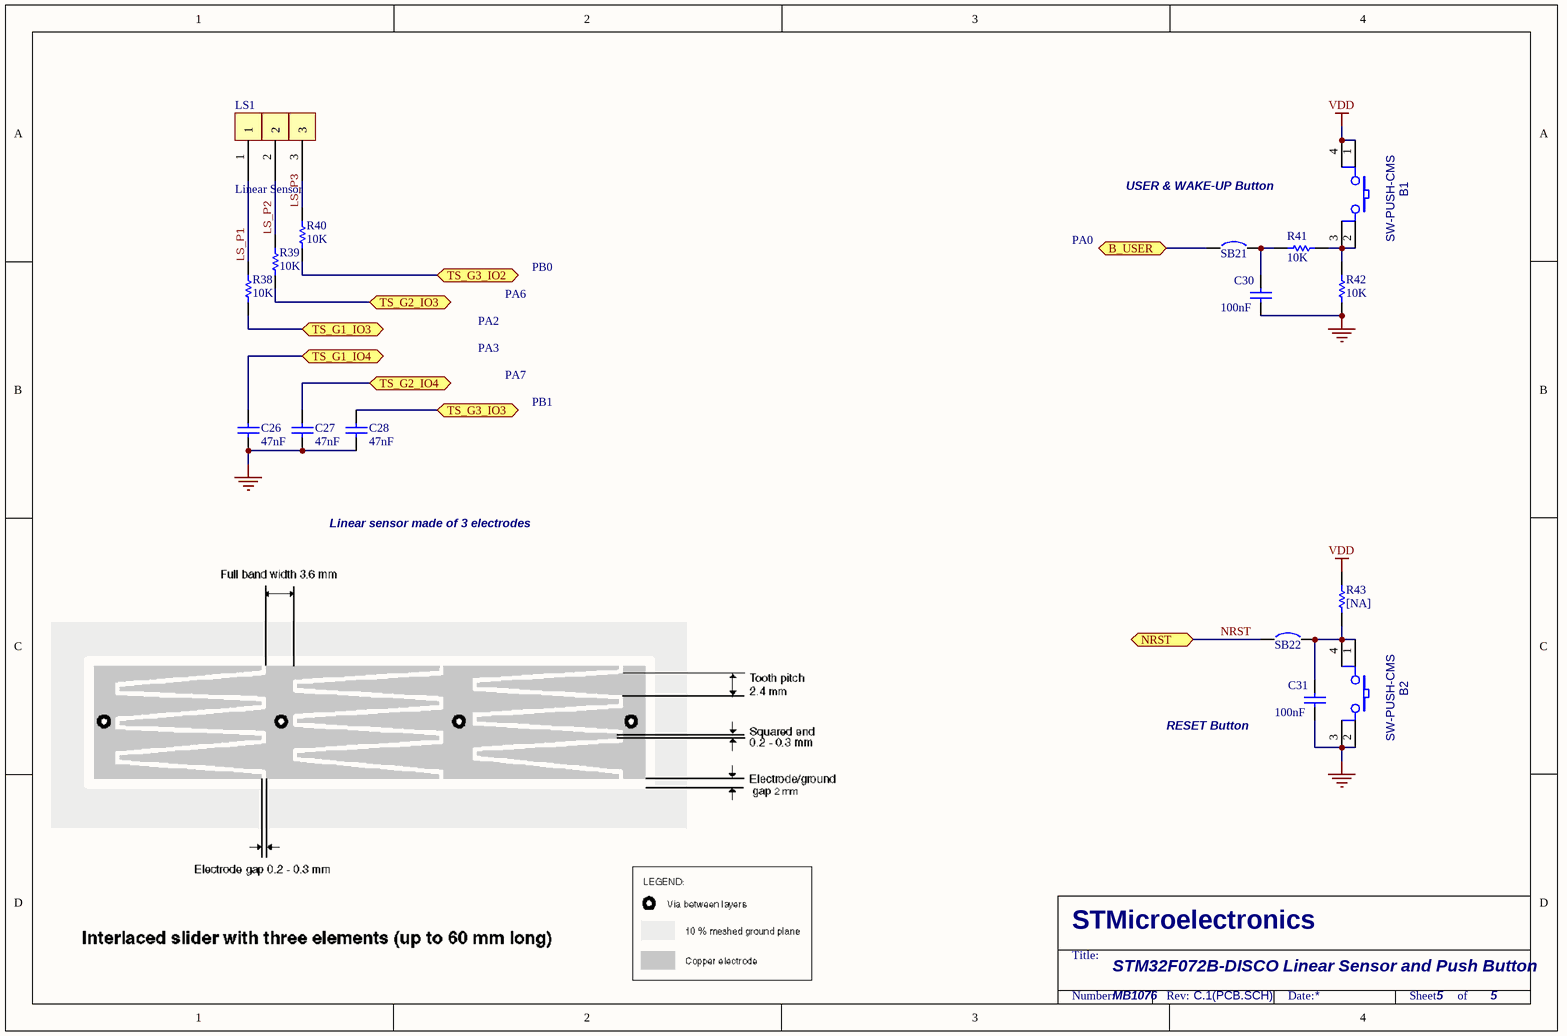
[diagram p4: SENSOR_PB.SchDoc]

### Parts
B1  SW-PUSH-CMS  [BP1CMS]
B2  SW-PUSH-CMS  [BP1CMS]
C26  47nF  [0805C]
C27  47nF  [0805C]
C28  47nF  [0805C]
C30  100nF  [0402C]
C31  100nF  [0402C]
LS1  Linear Sensor  [Linear Sensor 3 electrodes]
R38  10K  [0402R]
R39  10K  [0402R]
R40  10K  [0402R]
R41  10K  [0402R]
R42  10K  [0402R]
R43  [NA]  [0402R]
SB21  Circuit Breaker  [JP2_SMD]  (value not drawn)
SB22  Circuit Breaker  [JP2_SMD]  (value not drawn)

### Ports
B_USER, NRST, TS_G1_IO3, TS_G1_IO4, TS_G2_IO3, TS_G2_IO4, TS_G3_IO2, TS_G3_IO3

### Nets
GND: B2.2 B2.3 C26.1 C27.1 C28.1 C30.1 C31.1 R42.1
VDD: B1.1 B1.4 R43.2
B_USER: SB21.1 ; port B_USER
LS_P1: LS1.1 R38.2
LS_P2: LS1.2 R39.2
LS_P3: LS1.3 R40.2
NRST: SB22.1 ; port NRST
TS_G1_IO3: R38.1 ; port TS_G1_IO3
TS_G1_IO4: C26.2 ; port TS_G1_IO4
TS_G2_IO3: R39.1 ; port TS_G2_IO3
TS_G2_IO4: C27.2 ; port TS_G2_IO4
TS_G3_IO2: R40.1 ; port TS_G3_IO2
TS_G3_IO3: C28.2 ; port TS_G3_IO3
NetB1_2: B1.2 B1.3 R41.2 R42.2
NetB2_1: B2.1 B2.4 C31.2 R43.1 SB22.2
NetC30_2: C30.2 R41.1 SB21.2

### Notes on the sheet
- PA0
- USER & WAKE-UP Button
- PA6
- PB0
- PA2
- PA3
- PA7
- PB1
- Linear sensor made of 3 electrodes
- RESET Button
- STM32F072B-DISCO Linear Sensor and Push Button
- MB1076

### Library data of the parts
B1 B2 = SW-PUSH-CMS: Non-Open Push-Button 0.1A 24V; Manuf_1: FARNELL; Manuf_Part_1: 535-930; Ref St: 9180120; cap_dec: ---
C26-C28 = Cap_47nF_NPO_5%: Capacitor 47nF,5%,25V,NPO,0805 Kemet; Description: capacitor,47nF,5%,25V,NPO,0805 Kemet; Order: C0805C473J3GACTU
C30 C31 = Capacitor_ST: Capacitor 0402 / 0603 / 0805
LS1 = Linear Sensor 3 pos: plan de cuivre recouvert de vernis + Couche Plastic
R38-R42 = Resistor_ST: as R16 on sheet ST_LINK_V2
R43 = Resistor_ST: as R15 on sheet ST_LINK_V2
SB21 SB22 = Circuit Breaker: Solder: YES

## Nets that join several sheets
3V: MB1076 (P1.1), ST_LINK_V2 (17 pins), MEMS_USB (8 pins)
5V: MB1076 (P2.1), ST_LINK_V2 (5 pins), MEMS_USB (CN3.8 D2.2)
GND: MB1076 (5 pins), ST_LINK_V2 (33 pins), MEMS_USB (19 pins), STM32Fx (17 pins), SENSOR_PB (8 pins)
VBAT: MB1076 (P1.3), STM32Fx (C16.1 C17.2 SB15.2 U4.1)
VDD: MB1076 (P2.5), ST_LINK_V2 (JP2.2), STM32Fx (8 pins), SENSOR_PB (B1.1 B1.4 R43.2)
VDD_USB: MB1076 (P2.18), STM32Fx (C21.2 SB16.2 U4.48)
VDDA: MB1076 (P2.19), STM32Fx (C24.2 C25.1 SB26.2 U4.13)
B_USER: MB1076 (P1.15), STM32Fx (U4.14), SENSOR_PB (SB21.1)
BOOT0: MB1076 (P2.6), STM32Fx (R33.1 U4.60)
EXT_RESET: MB1076 (P1.26), MEMS_USB (CN3.4), STM32Fx (U4.25)
I2C2_SCL: MB1076 (P1.30), MEMS_USB (CN3.3 R2.1), STM32Fx (U4.29)
I2C2_SDA: MB1076 (P1.31), MEMS_USB (CN3.1 R1.1), STM32Fx (U4.30)
LD_D: MB1076 (P2.28), MEMS_USB (R31.1), STM32Fx (U4.38)
LD_L: MB1076 (P2.27), MEMS_USB (R32.1), STM32Fx (U4.39)
LD_R: MB1076 (P2.26), MEMS_USB (R30.1), STM32Fx (U4.40)
LD_U: MB1076 (P2.29), MEMS_USB (R29.1), STM32Fx (U4.37)
MCO: ST_LINK_V2 (C32.2 R44.2), STM32Fx (SB19.1)
MEMS_INT1: MB1076 (P1.12), MEMS_USB (U3.7), STM32Fx (U4.9)
MEMS_INT2: MB1076 (P1.13), MEMS_USB (U3.6), STM32Fx (U4.10)
NCS_MEMS_SPI: MB1076 (P1.11), MEMS_USB (U3.5), STM32Fx (U4.8)
NRST: MB1076 (P1.10), ST_LINK_V2 (SB10.2), STM32Fx (U4.7), SENSOR_PB (SB22.1)
PA1: MB1076 (P1.16), STM32Fx (U4.15)
PA2: MB1076 (P1.17), STM32Fx (SB27.1)
PA3: MB1076 (P1.18), STM32Fx (SB28.1)
PA4: MB1076 (P1.21), STM32Fx (U4.20)
PA5: MB1076 (P1.22), STM32Fx (U4.21)
PA6: MB1076 (P1.23), STM32Fx (SB29.1)
PA7: MB1076 (P1.24), STM32Fx (SB30.1)
PA8: MB1076 (P2.25), STM32Fx (U4.41)
PA9: MB1076 (P2.24), ST_LINK_V2 (SB12.1), STM32Fx (U4.42)
PA10: MB1076 (P2.23), ST_LINK_V2 (SB11.1), STM32Fx (U4.43)
PA11: MB1076 (P2.22), STM32Fx (SB23.1)
PA12: MB1076 (P2.21), STM32Fx (SB20.1)
PA13: MB1076 (P2.20), ST_LINK_V2 (SB9.1), STM32Fx (U4.46)
PA14: MB1076 (P2.17), ST_LINK_V2 (SB4.1), STM32Fx (U4.49)
PA15: MB1076 (P2.16), STM32Fx (U4.50)
PB0: MB1076 (P1.27), STM32Fx (SB31.1)
PB1: MB1076 (P1.28), STM32Fx (SB32.1)
PB2: MB1076 (P1.29), STM32Fx (U4.28)
PB3: MB1076 (P2.11), STM32Fx (U4.55)
PB4: MB1076 (P2.10), STM32Fx (U4.56)
PB5: MB1076 (P2.9), STM32Fx (U4.57)
PB6: MB1076 (P2.8), STM32Fx (U4.58)
PB7: MB1076 (P2.7), STM32Fx (U4.59)
PB8: MB1076 (P2.4), STM32Fx (U4.61)
PB9: MB1076 (P2.3), STM32Fx (U4.62)
PB12: MB1076 (P1.32), STM32Fx (U4.33)
PB13: MB1076 (P2.32), MEMS_USB (U3.2), STM32Fx (U4.34)
PB14: MB1076 (P2.31), MEMS_USB (U3.4), STM32Fx (U4.35)
PB15: MB1076 (P2.30), MEMS_USB (U3.3), STM32Fx (U4.36)
PC3: MB1076 (P1.14), STM32Fx (U4.11)
PC4: MB1076 (P1.25), STM32Fx (U4.24)
PC10: MB1076 (P2.15), STM32Fx (U4.51)
PC11: MB1076 (P2.14), STM32Fx (U4.52)
PC12: MB1076 (P2.13), STM32Fx (U4.53)
PC13: MB1076 (P1.4), STM32Fx (U4.2)
PC14: MB1076 (P1.5), STM32Fx (SB14.1)
PC15: MB1076 (P1.6), STM32Fx (SB13.1)
PD2: MB1076 (P2.12), STM32Fx (U4.54)
PF0: MB1076 (P1.7), STM32Fx (SB17.1)
PF1: MB1076 (P1.8), STM32Fx (SB18.1)
TS_G1_IO3: STM32Fx (SB27.2 U4.16), SENSOR_PB (R38.1)
TS_G1_IO4: STM32Fx (SB28.2 U4.17), SENSOR_PB (C26.2)
TS_G2_IO3: STM32Fx (SB29.2 U4.22), SENSOR_PB (R39.1)
TS_G2_IO4: STM32Fx (SB30.2 U4.23), SENSOR_PB (C27.2)
TS_G3_IO2: STM32Fx (SB31.2 U4.26), SENSOR_PB (R40.1)
TS_G3_IO3: STM32Fx (SB32.2 U4.27), SENSOR_PB (C28.2)
USBF4_DM: MEMS_USB (R13.2), STM32Fx (SB23.2 U4.44)
USBF4_DP: MEMS_USB (R12.2), STM32Fx (SB20.2 U4.45)
VDD3: MB1076 (P1.20), STM32Fx (C33.1 SB25.1 U4.19)
VSS3: MB1076 (P1.19), STM32Fx (C33.2 SB24.1 U4.18)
